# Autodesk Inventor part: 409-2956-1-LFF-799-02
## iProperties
Created: 2010-11
Part Number: 409-2956-1-LFF-799-02
Material: 3/4" OD TUBE - SS
Document SubType Name: Modeling
Designer: S. Boerckel
Engineer: Steve Boerckel
Mass: 309.983 g
Surface Area: 466.545 cm^2
Volume: 38.3643 cm^3
Density: 8.08 g/cm^3
Description: DRAIN TUBING
Length: 22.332 in
Author: S. Boerckel
Revision Number: 0
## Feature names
1. Sweep1
